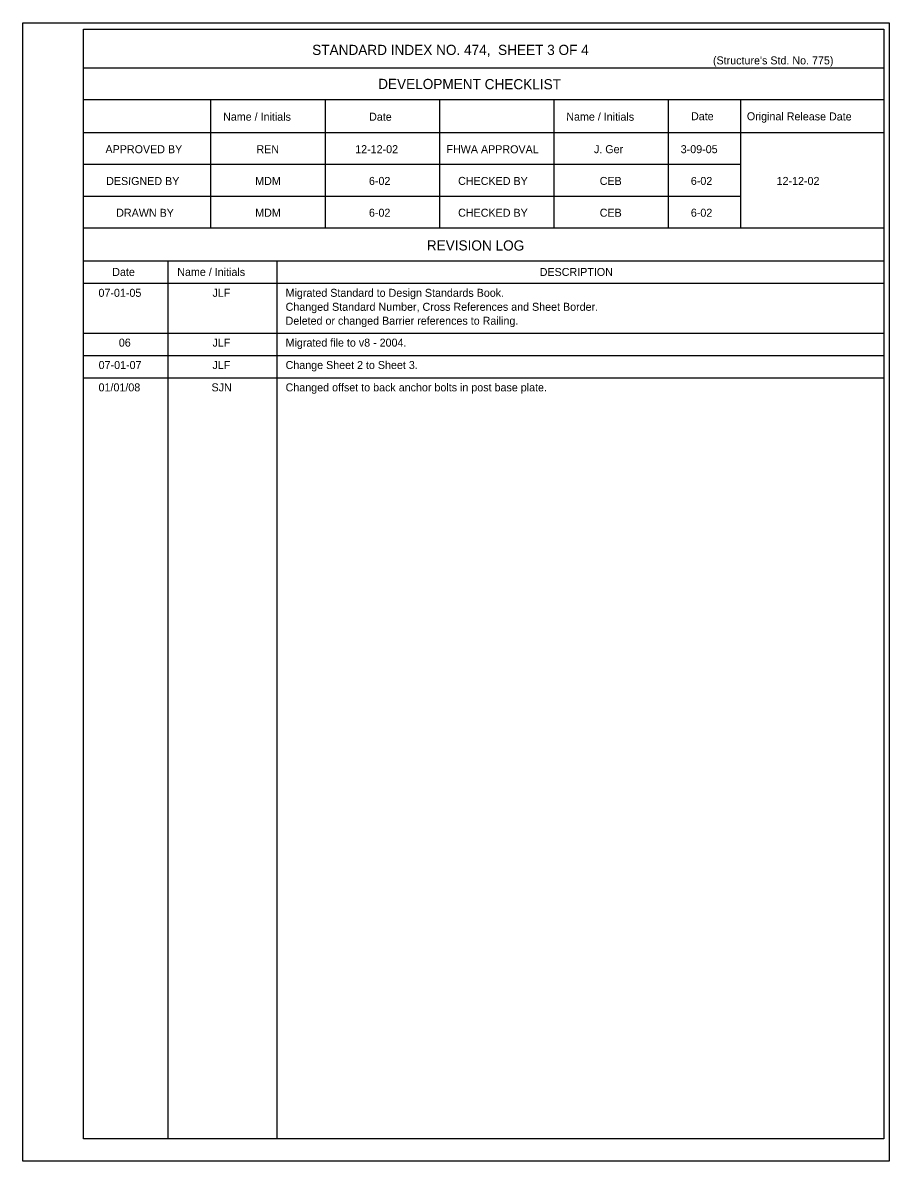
# Model space of a CAD drawing. Extents: x 21665 to 21741.5, y 56121.9 to 56164.2.
# Drawn here: x 21719.64 to 21741.46, y 56130.93 to 56159.6 of the extents above; entities that cross this region are included whole.
import ezdxf

# ---------------------------------------------------------------- set-up
doc = ezdxf.new("R2010")
doc.units = 0
for name, color, linetype in [('Border', 7, 'Continuous'), ('Dimension', 7, 'Continuous'), ('PlotBorder_dp', 7, 'Continuous'), ('TextStructures', 7, 'Continuous')]:
    doc.layers.add(name, color=color, linetype=linetype)

msp = doc.modelspace()

# ---------------------------------------------------------------- linework, layer by layer
at = {"layer": 'Border'}
for p, q in [((21741.319, 56158.455), (21721.172, 56158.455)), ((21741.319, 56157.655), (21721.172, 56157.655)), ((21724.372, 56157.655), (21724.372, 56154.427)), ((21727.252, 56157.655), (21727.252, 56154.427)), ((21730.132, 56157.655), (21730.132, 56154.427)), ((21733.012, 56157.655), (21733.012, 56154.427)), ((21735.892, 56157.655), (21735.892, 56154.427)), ((21737.707, 56157.655), (21737.707, 56154.427)), ((21741.319, 56156.827), (21721.172, 56156.827)), ((21737.707, 56156.027), (21721.172, 56156.027)), ((21737.707, 56155.227), (21721.172, 56155.227)), ((21741.319, 56154.427), (21721.172, 56154.427)), ((21741.319, 56153.599), (21721.172, 56153.599)), ((21723.293, 56153.599), (21723.293, 56131.492)), ((21726.035, 56153.599), (21726.035, 56131.492)), ((21741.319, 56153.035), (21721.172, 56153.035))]:
    msp.add_line(p, q, dxfattribs=at)
msp.add_lwpolyline([(21721.173, 56159.435), (21741.319, 56159.435), (21741.319, 56131.492), (21721.173, 56131.492)], close=True, dxfattribs=at)
at = {"layer": 'Dimension'}
for p, q in [((21721.173, 56151.781), (21741.319, 56151.781)), ((21721.173, 56151.217), (21741.319, 56151.217)), ((21721.173, 56150.654), (21741.319, 56150.654))]:
    msp.add_line(p, q, dxfattribs=at)
at = {"layer": 'PlotBorder_dp'}
msp.add_line((21719.642, 56130.931), (21719.642, 56130.931), dxfattribs=at)
msp.add_lwpolyline([(21719.642, 56159.598), (21741.455, 56159.598), (21741.455, 56130.931), (21719.642, 56130.931)], close=True, dxfattribs=at)

# ---------------------------------------------------------------- texts
at = {"layer": 'TextStructures'}
for s, height, p in [('STANDARD INDEX NO. 474,  SHEET 3 OF 4', 0.256, (21726.928, 56158.787)), ("(Structure's Std. No. 775)", 0.2016, (21737.018, 56158.549)), ('REN', 0.2016, (21725.524, 56156.314)), ('12-12-02', 0.2016, (21728.011, 56156.314)), ('J. Ger', 0.2016, (21734.022, 56156.314)), ('3-09-05', 0.2016, (21736.206, 56156.314)), ('MDM', 0.2016, (21725.493, 56155.514)), ('6-02', 0.2016, (21728.357, 56155.514)), ('CEB', 0.2016, (21734.167, 56155.514)), ('6-02', 0.2016, (21736.461, 56155.514)), ('12-12-02', 0.2016, (21738.62, 56155.514)), ('MDM', 0.2016, (21725.493, 56154.714)), ('6-02', 0.2016, (21728.357, 56154.714)), ('CEB', 0.2016, (21734.167, 56154.714)), ('6-02', 0.2016, (21736.461, 56154.714)), ('DESCRIPTION', 0.2016, (21732.656, 56153.222)), ('07-01-05', 0.2016, (21721.548, 56152.697)), ('JLF', 0.2016, (21724.419, 56152.697)), ('Migrated Standard to Design Standards Book.', 0.2016, (21726.259, 56152.697)), ('Changed Standard Number, Cross References and Sheet Border.', 0.2016, (21726.259, 56152.345)), ('Deleted or changed Barrier references to Railing.', 0.2016, (21726.259, 56151.994)), ('06', 0.2016, (21722.06, 56151.443)), ('JLF', 0.2016, (21724.419, 56151.443)), ('Migrated file to v8 - 2004.', 0.2016, (21726.259, 56151.443)), ('07-01-07', 0.2016, (21721.552, 56150.879)), ('JLF', 0.2016, (21724.419, 56150.879)), ('Change Sheet 2 to Sheet 3.', 0.2016, (21726.259, 56150.879)), ('01/01/08', 0.2016, (21721.55, 56150.316)), ('SJN', 0.2016, (21724.394, 56150.316)), ('Changed offset to back anchor bolts in post base plate.', 0.2016, (21726.259, 56150.316))]:
    msp.add_text(s, height=height, dxfattribs=at).set_placement(p)
for s, height, p in [('DEVELOPMENT CHECKLIST', 0.256, (21728.588, 56157.931)), ('Name / Initials', 0.2016, (21724.685, 56157.134)), ('Date', 0.2016, (21728.36, 56157.132)), ('Name / Initials', 0.2016, (21733.325, 56157.134)), ('Date', 0.2016, (21736.465, 56157.144)), ('Original Release Date', 0.2016, (21737.871, 56157.143)), ('APPROVED BY', 0.2016, (21721.724, 56156.315)), ('FHWA APPROVAL', 0.2016, (21730.308, 56156.315)), ('DESIGNED BY', 0.2016, (21721.741, 56155.514)), ('CHECKED BY', 0.2016, (21730.602, 56155.515)), ('DRAWN BY', 0.2016, (21721.994, 56154.714)), ('CHECKED BY', 0.2016, (21730.602, 56154.715)), ('REVISION LOG', 0.256, (21729.813, 56153.866)), ('Date', 0.2016, (21721.895, 56153.223)), ('Name / Initials', 0.2016, (21723.531, 56153.224))]:
    msp.add_text(s, height=height, rotation=359.8756, dxfattribs=at).set_placement(p)

doc.saveas('drawing.dxf')
